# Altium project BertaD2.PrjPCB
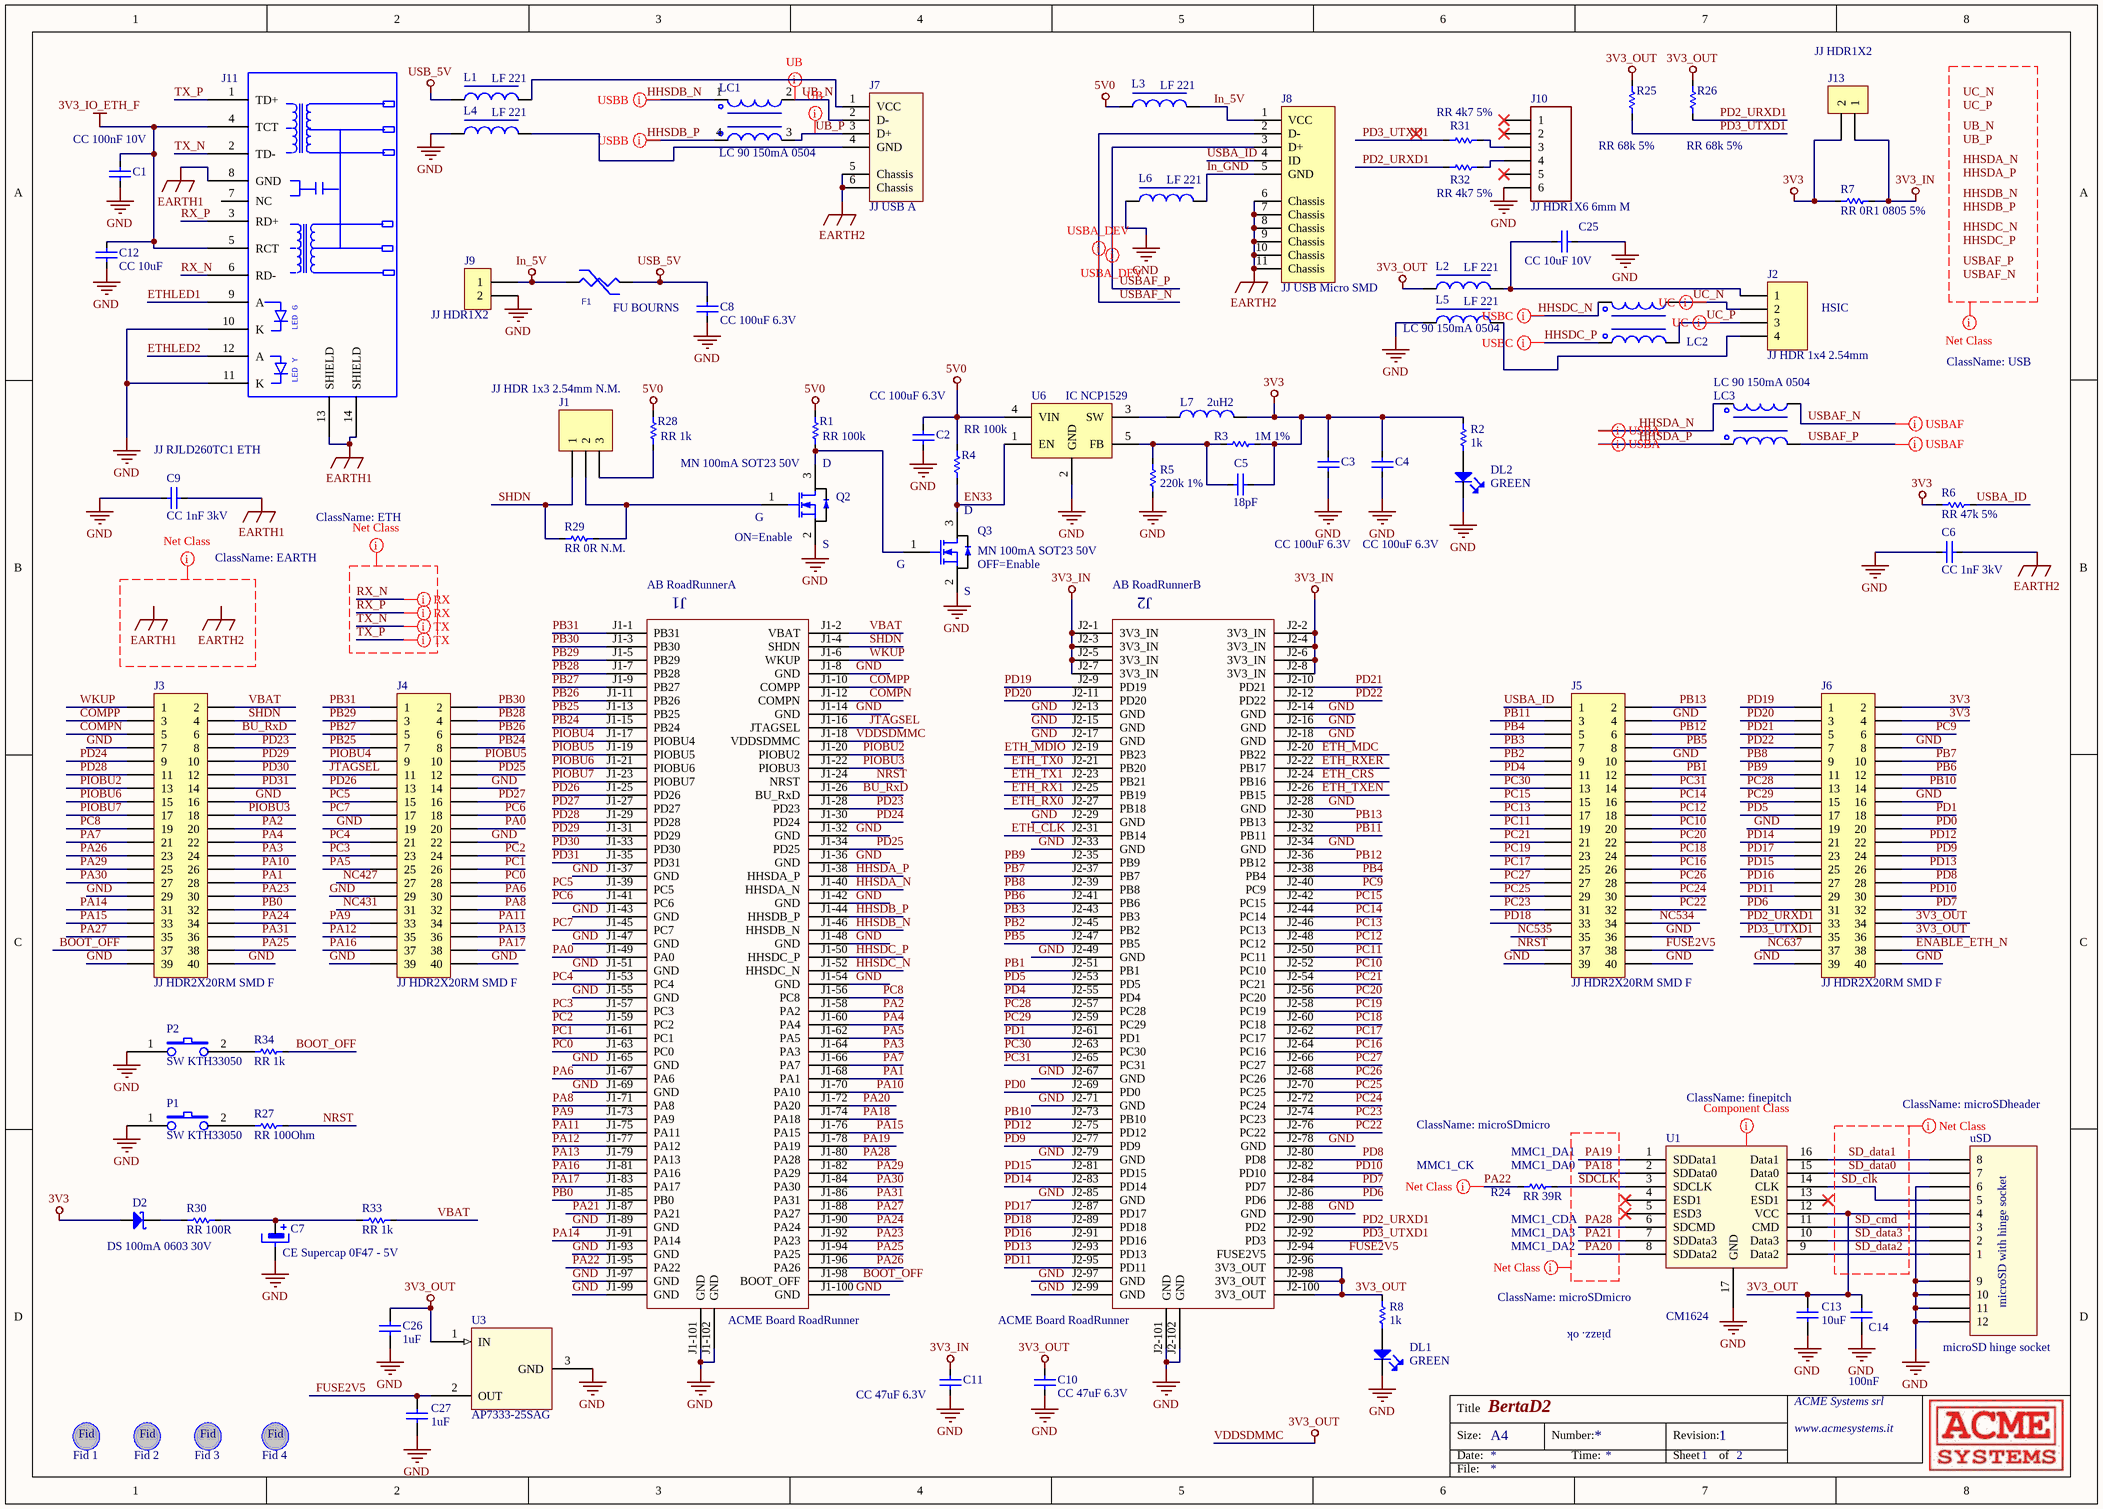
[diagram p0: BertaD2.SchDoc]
2 sheets, 108 parts. Net scope: global (net labels, ports and power ports of the same name join across sheets).
Board files: BertaD2_pan.PCBDOC, BertaD2.PcbDoc
Sheets:
  BertaD2.SchDoc
  BertaD2_ETH.SchDoc

## Sheet BertaD2.SchDoc: BertaD2
size A3; Organization: ACME Systems srl; Address2: www.acmesystems.it; Revision: 1; SheetNumber: 1; SheetTotal: 2

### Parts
AB_RoadRunner  ACME Board RoadRunner  [AB RoadRunner]  (parts A,B of 2)
C1  CC 100nF 10V  [CC 0402S 1005m SOLDER]
C2  CC 100uF 6.3V  [CC 1206 (3216 metric)]
C3  CC 100uF 6.3V  [CC 1206 (3216 metric)]
C4  CC 100uF 6.3V  [CC 1206 (3216 metric)]
C5  18pF  [CC 0402S 1005m SOLDER]
C6  CC 1nF 3kV  [CC 1808 (4520 metric)]
C7  CE Supercap 0F47 - 5V  [Supercap AVX 8x16x18]
C8  CC 100uF 6.3V  [CC 1206 (3216 metric)]
C9  CC 1nF 3kV  [CC 1808 (4520 metric)]
C10  CC 47uF 6.3V  [CC 1206 (3216 metric)]
C11  CC 47uF 6.3V  [CC 1206 (3216 metric)]
C12  CC 10uF  [CC 0805 (2012 metric)]
C13  10uF  [CC 0805 (2012 metric)]
C14  100nF  [CC 0402S 1005m SOLDER]
C25  CC 10uF 10V  [CC 0805 (2012 metric)]
C26  1uF  [CC 0603 (1608 metric)]
C27  1uF  [CC 0603 (1608 metric)]
D2  DS 100mA 0603 30V  [DD 0603]
DL1  GREEN  [DL 0603 (1608 metric) GREEN]
DL2  GREEN  [DL 0603 (1608 metric) GREEN]
F1  FU BOURNS  [FU 1812 (4532 metric)]
Fid_1  FF ACME  [Fiducial 1mm_small]  (value not drawn)
Fid_2  FF ACME  [Fiducial 1mm_small]  (value not drawn)
Fid_3  FF ACME  [Fiducial 1mm_small]  (value not drawn)
Fid_4  FF ACME  [Fiducial 1mm_small]  (value not drawn)
J1  JJ HDR 1x3 2.54mm N.M.  [HDR 1x3]
J2  JJ HDR 1x4 2.54mm  [HDR1X4 - Female DualMount]
J3  JJ HDR2X20RM SMD F  [HDR2X20 SMD Female]
J4  JJ HDR2X20RM SMD F  [HDR2X20 SMD Female]
J5  JJ HDR2X20RM SMD F  [HDR2X20 SMD Female]
J6  JJ HDR2X20RM SMD F  [HDR2X20 SMD Female]
J7  JJ USB A  [USB2.0-4H4 3D FOX]
J8  JJ USB Micro SMD  [USB Micro B - Extended]
J9  JJ HDR1X2  [HDR1X2 NAKED]
J10  JJ HDR1X6 6mm M  [HDR1X6 3D]
J11  JJ RJLD260TC1 ETH  [RJLD-260TC1]
J13  JJ HDR1X2  [HDR1X2 NAKED]
L1  LF 221  [LL 0603 (1608 metric)]
L2  LF 221  [LL 0603 (1608 metric)]
L3  LF 221  [LL 0603 (1608 metric)]
L4  LF 221  [LL 0603 (1608 metric)]
L5  LF 221  [LL 0603 (1608 metric)]
L6  LF 221  [LL 0603 (1608 metric)]
L7  2uH2  [LL 0805 (2012 metric)]
LC1  LC 90 150mA 0504  [LC 0504 (1210 metric)]
LC2  LC 90 150mA 0504  [LC 0504 (1210 metric)]
LC3  LC 90 150mA 0504  [LC 0504 (1210 metric)]
P1  SW KTH33050  [PULSANTE SMD S]
P2  SW KTH33050  [PULSANTE SMD S]
Q2  MN 100mA SOT23 50V  [SOT23 for IRLML6402]
Q3  MN 100mA SOT23 50V  [SOT23 for IRLML6402]
R1  RR 100k  [CC 0402S 1005m SOLDER]
R2  1k  [CC 0402S 1005m SOLDER]
R3  1M 1%  [CC 0402S 1005m SOLDER]
R4  RR 100k  [CC 0402S 1005m SOLDER]
R5  220k 1%  [CC 0402S 1005m SOLDER]
R6  RR 47k 5%  [RR 0402S 1005m SOLDER]
R7  RR 0R1 0805 5%  [RR 1206 (3216 metric)]
R8  1k  [CC 0402S 1005m SOLDER]
R24  RR 39R  [RR 0402S 1005m SOLDER]
R25  RR 68k 5%  [RR 0402S 1005m SOLDER]
R26  RR 68k 5%  [RR 0402S 1005m SOLDER]
R27  RR 100Ohm  [CC 0402S 1005m SOLDER]
R28  RR 1k  [CC 0402S 1005m SOLDER]
R29  RR 0R N.M.  [CC 0402S 1005m SOLDER]
R30  RR 100R  [RR 0603 (1608 metric)]
R31  RR 4k7 5%  [RR 0402S 1005m SOLDER]
R32  RR 4k7 5%  [RR 0402S 1005m SOLDER]
R33  RR 1k  [CC 0402S 1005m SOLDER]
R34  RR 1k  [CC 0402S 1005m SOLDER]
U1  CM1624  [CM1624]
U3  AP7333-25SAG  [SOT23 generic]
U6  IC NCP1529  [IC SOT23-5]
uSD  microSD hinge socket  [microSDHinge JAE E]

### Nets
3V3: C3.1 C4.1 C5.2 D2.A J6.2 J6.4 J13.2 L7.2 R2.1 R3.2 R6.1 R7.1
3V3_IN: AB_RoadRunner.J2-1(3V3_IN) AB_RoadRunner.J2-2(3V3_IN) AB_RoadRunner.J2-3(3V3_IN) AB_RoadRunner.J2-4(3V3_IN) AB_RoadRunner.J2-5(3V3_IN) AB_RoadRunner.J2-6(3V3_IN) AB_RoadRunner.J2-7(3V3_IN) AB_RoadRunner.J2-8(3V3_IN) C11.1 J13.1 R7.2
3V3_IO_ETH_F: C1.1 C12.1 J11.4(TCT) J11.5(RCT)
3V3_OUT: AB_RoadRunner.J1-18(VDDSDMMC) AB_RoadRunner.J2-96(3V3_OUT) AB_RoadRunner.J2-98(3V3_OUT) AB_RoadRunner.J2-100(3V3_OUT) C10.1 C13.1 C14.1 C26.2 J6.34 J6.36 L2.1 R8.1 R25.2 R26.2 U1.12(VCC) U3.1(IN) uSD.4  [also labelled VDDSDMMC]
5V0: C2.1 L3.1 R1.1 R4.1 R28.1 U6.4(VIN)
EARTH1: C9.2 J11.8(GND) J11.13(SHIELD) J11.14(SHIELD)
EARTH2: C6.2 J7.5(Chassis) J7.6(Chassis) J8.6(Chassis) J8.7(Chassis) J8.8(Chassis) J8.9(Chassis) J8.10(Chassis) J8.11(Chassis)
GND: AB_RoadRunner.J1-8(GND) AB_RoadRunner.J1-14(GND) AB_RoadRunner.J1-32(GND) AB_RoadRunner.J1-36(GND) AB_RoadRunner.J1-37(GND) AB_RoadRunner.J1-42(GND) AB_RoadRunner.J1-43(GND) AB_RoadRunner.J1-47(GND) AB_RoadRunner.J1-48(GND) AB_RoadRunner.J1-51(GND) AB_RoadRunner.J1-54(GND) AB_RoadRunner.J1-55(GND) AB_RoadRunner.J1-65(GND) AB_RoadRunner.J1-69(GND) AB_RoadRunner.J1-89(GND) AB_RoadRunner.J1-93(GND) AB_RoadRunner.J1-97(GND) AB_RoadRunner.J1-99(GND) AB_RoadRunner.J1-100(GND) AB_RoadRunner.J1-101(GND) AB_RoadRunner.J1-102(GND) AB_RoadRunner.J2-13(GND) AB_RoadRunner.J2-14(GND) AB_RoadRunner.J2-15(GND) AB_RoadRunner.J2-16(GND) AB_RoadRunner.J2-17(GND) AB_RoadRunner.J2-18(GND) AB_RoadRunner.J2-28(GND) AB_RoadRunner.J2-29(GND) AB_RoadRunner.J2-33(GND) AB_RoadRunner.J2-34(GND) AB_RoadRunner.J2-49(GND) AB_RoadRunner.J2-67(GND) AB_RoadRunner.J2-71(GND) AB_RoadRunner.J2-78(GND) AB_RoadRunner.J2-79(GND) AB_RoadRunner.J2-85(GND) AB_RoadRunner.J2-88(GND) AB_RoadRunner.J2-97(GND) AB_RoadRunner.J2-99(GND) AB_RoadRunner.J2-101(GND) AB_RoadRunner.J2-102(GND) C1.2 C2.2 C3.2 C4.2 C6.1 C7.2 C8.2 C9.1 C10.2 C11.2 C12.2 C13.2 C14.2 C25.2 C26.1 C27.2 DL1.K DL2.K J3.7 J3.16 J3.29 J3.39 J3.40 J4.14 J4.19 J4.22 J4.29 J4.39 J4.40 J5.4 J5.10 J5.36 J5.39 J5.40 J6.8 J6.16 J6.19 J6.39 J6.40 J9.2 J10.6 J11.10(K) J11.11(K) L4.1 L5.1 L6.1 P1.1 P2.1 Q2.2(S) Q3.2(S) R5.2 U1.17(GND) U3.3(GND) U6.2(GND) uSD.6 uSD.9 uSD.10 uSD.11 uSD.12
In_5V: F1.1 J8.1(VCC) J9.1 L3.2
USB_5V: C8.1 F1.2 L1.1
BOOT_OFF: AB_RoadRunner.J1-98(BOOT_OFF) J3.37 R34.2
BU_RxD: AB_RoadRunner.J1-26(BU_RxD) J3.6
COMPN: AB_RoadRunner.J1-12(COMPN) J3.5
COMPP: AB_RoadRunner.J1-10(COMPP) J3.3
EN33: Q3.3(D) R4.2 U6.1(EN)
ENABLE_ETH_N: J6.38
ETH_CLK: AB_RoadRunner.J2-31(PB14)
ETH_CRS: AB_RoadRunner.J2-24(PB16)
ETH_MDC: AB_RoadRunner.J2-20(PB22)
ETH_MDIO: AB_RoadRunner.J2-19(PB23)
ETH_RX0: AB_RoadRunner.J2-27(PB18)
ETH_RX1: AB_RoadRunner.J2-25(PB19)
ETH_RXER: AB_RoadRunner.J2-22(PB17)
ETH_TX0: AB_RoadRunner.J2-21(PB20)
ETH_TX1: AB_RoadRunner.J2-23(PB21)
ETH_TXEN: AB_RoadRunner.J2-26(PB15)
ETHLED1: J11.9(A)
ETHLED2: J11.12(A)
FUSE2V5: AB_RoadRunner.J2-94(FUSE2V5) C27.1 J5.38 U3.2(OUT)
HHSDA_N: AB_RoadRunner.J1-40(HHSDA_N) LC3.4
HHSDA_P: AB_RoadRunner.J1-38(HHSDA_P) LC3.1
HHSDB_N: AB_RoadRunner.J1-46(HHSDB_N) LC1.1
HHSDB_P: AB_RoadRunner.J1-44(HHSDB_P) LC1.4
HHSDC_N: AB_RoadRunner.J1-52(HHSDC_N) LC2.4
HHSDC_P: AB_RoadRunner.J1-50(HHSDC_P) LC2.1
In_GND: J8.5(GND) L6.2
JTAGSEL: AB_RoadRunner.J1-16(JTAGSEL) J4.11
NC427: J4.27
NC431: J4.31
NC534: J5.34
NC535: J5.35
NC637: J6.37
NRST: AB_RoadRunner.J1-24(NRST) J5.37 R27.2
PA0: AB_RoadRunner.J1-49(PA0) J4.20
PA1: AB_RoadRunner.J1-68(PA1) J3.28
PA2: AB_RoadRunner.J1-58(PA2) J3.20
PA3: AB_RoadRunner.J1-64(PA3) J3.24
PA4: AB_RoadRunner.J1-60(PA4) J3.22
PA5: AB_RoadRunner.J1-62(PA5) J4.25
PA6: AB_RoadRunner.J1-67(PA6) J4.30
PA7: AB_RoadRunner.J1-66(PA7) J3.21
PA8: AB_RoadRunner.J1-71(PA8) J4.32
PA9: AB_RoadRunner.J1-73(PA9) J4.33
PA10: AB_RoadRunner.J1-70(PA10) J3.26
PA11: AB_RoadRunner.J1-75(PA11) J4.34
PA12: AB_RoadRunner.J1-77(PA12) J4.35
PA13: AB_RoadRunner.J1-79(PA13) J4.36
PA14: AB_RoadRunner.J1-91(PA14) J3.31
PA15: AB_RoadRunner.J1-76(PA15) J3.33
PA16: AB_RoadRunner.J1-81(PA16) J4.37
PA17: AB_RoadRunner.J1-83(PA17) J4.38
PA18: AB_RoadRunner.J1-74(PA18) U1.2(SDData0)
PA19: AB_RoadRunner.J1-78(PA19) U1.1(SDData1)
PA20: AB_RoadRunner.J1-72(PA20) U1.8(SDData2)
PA21: AB_RoadRunner.J1-87(PA21) U1.7(SDData3)
PA22: AB_RoadRunner.J1-95(PA22) R24.1
PA23: AB_RoadRunner.J1-92(PA23) J3.30
PA24: AB_RoadRunner.J1-90(PA24) J3.34
PA25: AB_RoadRunner.J1-94(PA25) J3.38
PA26: AB_RoadRunner.J1-96(PA26) J3.23
PA27: AB_RoadRunner.J1-88(PA27) J3.35
PA28: AB_RoadRunner.J1-80(PA28) U1.6(SDCMD)
PA29: AB_RoadRunner.J1-82(PA29) J3.25
PA30: AB_RoadRunner.J1-84(PA30) J3.27
PA31: AB_RoadRunner.J1-86(PA31) J3.36
PB0: AB_RoadRunner.J1-85(PB0) J3.32
PB1: AB_RoadRunner.J2-51(PB1) J5.12
PB2: AB_RoadRunner.J2-45(PB2) J5.9
PB3: AB_RoadRunner.J2-43(PB3) J5.7
PB4: AB_RoadRunner.J2-38(PB4) J5.5
PB5: AB_RoadRunner.J2-47(PB5) J5.8
PB6: AB_RoadRunner.J2-41(PB6) J6.12
PB7: AB_RoadRunner.J2-37(PB7) J6.10
PB8: AB_RoadRunner.J2-39(PB8) J6.9
PB9: AB_RoadRunner.J2-35(PB9) J6.11
PB10: AB_RoadRunner.J2-73(PB10) J6.14
PB11: AB_RoadRunner.J2-32(PB11) J5.3
PB12: AB_RoadRunner.J2-36(PB12) J5.6
PB13: AB_RoadRunner.J2-30(PB13) J5.2
PB24: AB_RoadRunner.J1-15(PB24) J4.8
PB25: AB_RoadRunner.J1-13(PB25) J4.7
PB26: AB_RoadRunner.J1-11(PB26) J4.6
PB27: AB_RoadRunner.J1-9(PB27) J4.5
PB28: AB_RoadRunner.J1-7(PB28) J4.4
PB29: AB_RoadRunner.J1-5(PB29) J4.3
PB30: AB_RoadRunner.J1-3(PB30) J4.2
PB31: AB_RoadRunner.J1-1(PB31) J4.1
PC0: AB_RoadRunner.J1-63(PC0) J4.28
PC1: AB_RoadRunner.J1-61(PC1) J4.26
PC2: AB_RoadRunner.J1-59(PC2) J4.24
PC3: AB_RoadRunner.J1-57(PC3) J4.23
PC4: AB_RoadRunner.J1-53(PC4) J4.21
PC5: AB_RoadRunner.J1-39(PC5) J4.15
PC6: AB_RoadRunner.J1-41(PC6) J4.18
PC7: AB_RoadRunner.J1-45(PC7) J4.17
PC8: AB_RoadRunner.J1-56(PC8) J3.19
PC9: AB_RoadRunner.J2-40(PC9) J6.6
PC10: AB_RoadRunner.J2-52(PC10) J5.20
PC11: AB_RoadRunner.J2-50(PC11) J5.19
PC12: AB_RoadRunner.J2-48(PC12) J5.18
PC13: AB_RoadRunner.J2-46(PC13) J5.17
PC14: AB_RoadRunner.J2-44(PC14) J5.16
PC15: AB_RoadRunner.J2-42(PC15) J5.15
PC16: AB_RoadRunner.J2-64(PC16) J5.26
PC17: AB_RoadRunner.J2-62(PC17) J5.25
PC18: AB_RoadRunner.J2-60(PC18) J5.24
PC19: AB_RoadRunner.J2-58(PC19) J5.23
PC20: AB_RoadRunner.J2-56(PC20) J5.22
PC21: AB_RoadRunner.J2-54(PC21) J5.21
PC22: AB_RoadRunner.J2-76(PC22) J5.32
PC23: AB_RoadRunner.J2-74(PC23) J5.31
PC24: AB_RoadRunner.J2-72(PC24) J5.30
PC25: AB_RoadRunner.J2-70(PC25) J5.29
PC26: AB_RoadRunner.J2-68(PC26) J5.28
PC27: AB_RoadRunner.J2-66(PC27) J5.27
PC28: AB_RoadRunner.J2-57(PC28) J6.13
PC29: AB_RoadRunner.J2-59(PC29) J6.15
PC30: AB_RoadRunner.J2-63(PC30) J5.13
PC31: AB_RoadRunner.J2-65(PC31) J5.14
PD0: AB_RoadRunner.J2-69(PD0) J6.20
PD1: AB_RoadRunner.J2-61(PD1) J6.18
PD2_URXD1: AB_RoadRunner.J2-90(PD2) J6.33 R26.1 R32.2
PD3_UTXD1: AB_RoadRunner.J2-92(PD3) J6.35 R25.1 R31.2
PD4: AB_RoadRunner.J2-55(PD4) J5.11
PD5: AB_RoadRunner.J2-53(PD5) J6.17
PD6: AB_RoadRunner.J2-86(PD6) J6.31
PD7: AB_RoadRunner.J2-84(PD7) J6.32
PD8: AB_RoadRunner.J2-80(PD8) J6.28
PD9: AB_RoadRunner.J2-77(PD9) J6.24
PD10: AB_RoadRunner.J2-82(PD10) J6.30
PD11: AB_RoadRunner.J2-95(PD11) J6.29
PD12: AB_RoadRunner.J2-75(PD12) J6.22
PD13: AB_RoadRunner.J2-93(PD13) J6.26
PD14: AB_RoadRunner.J2-83(PD14) J6.21
PD15: AB_RoadRunner.J2-81(PD15) J6.25
PD16: AB_RoadRunner.J2-91(PD16) J6.27
PD17: AB_RoadRunner.J2-87(PD17) J6.23
PD18: AB_RoadRunner.J2-89(PD18) J5.33
PD19: AB_RoadRunner.J2-9(PD19) J6.1
PD20: AB_RoadRunner.J2-11(PD20) J6.3
PD21: AB_RoadRunner.J2-10(PD21) J6.5
PD22: AB_RoadRunner.J2-12(PD22) J6.7
PD23: AB_RoadRunner.J1-28(PD23) J3.8
PD24: AB_RoadRunner.J1-30(PD24) J3.9
PD25: AB_RoadRunner.J1-34(PD25) J4.12
PD26: AB_RoadRunner.J1-25(PD26) J4.13
PD27: AB_RoadRunner.J1-27(PD27) J4.16
PD28: AB_RoadRunner.J1-29(PD28) J3.11
PD29: AB_RoadRunner.J1-31(PD29) J3.10
PD30: AB_RoadRunner.J1-33(PD30) J3.12
PD31: AB_RoadRunner.J1-35(PD31) J3.14
PIOBU2: AB_RoadRunner.J1-20(PIOBU2) J3.13
PIOBU3: AB_RoadRunner.J1-22(PIOBU3) J3.18
PIOBU4: AB_RoadRunner.J1-17(PIOBU4) J4.9
PIOBU5: AB_RoadRunner.J1-19(PIOBU5) J4.10
PIOBU6: AB_RoadRunner.J1-21(PIOBU6) J3.15
PIOBU7: AB_RoadRunner.J1-23(PIOBU7) J3.17
RX_N: J11.6(RD-)
RX_P: J11.3(RD+)
SD_clk: U1.14(CLK) uSD.5
SD_cmd: U1.11(CMD) uSD.3
SD_data0: U1.15(Data0) uSD.7
SD_data1: U1.16(Data1) uSD.8
SD_data2: U1.9(Data2) uSD.1
SD_data3: U1.10(Data3) uSD.2
SDCLK: R24.2 U1.3(SDCLK)
SHDN: AB_RoadRunner.J1-4(SHDN) J1.1 J3.4 R29.1
TX_N: J11.2(TD-)
TX_P: J11.1(TD+)
UB_N: J7.2(D-) LC1.2
UB_P: J7.3(D+) LC1.3
UC_N: J2.2 LC2.3
UC_P: J2.3 LC2.2
USBA_ID: J5.1 J8.4(ID) R6.2
USBAF_N: J8.2(D-) LC3.3
USBAF_P: J8.3(D+) LC3.2
VBAT: AB_RoadRunner.J1-2(VBAT) J3.2 R33.2
WKUP: AB_RoadRunner.J1-6(WKUP) J3.1
NetC5_1: C5.1 R3.1 R5.1 U6.5(FB)
NetC7_1: C7.1 R30.2 R33.1
NetC25_1: C25.1 J2.1 L2.2
NetD2_K: D2.K R30.1
NetDL1_A: DL1.A R8.2
NetDL2_A: DL2.A R2.2
NetJ1_2: J1.2 Q2.1(G) R29.2
NetJ1_3: J1.3 R28.2
NetJ2_4: J2.4 L5.2
NetJ7_1: J7.1(VCC) L1.2
NetJ7_4: J7.4(GND) L4.2
NetJ10_3: J10.3 R31.1
NetJ10_4: J10.4 R32.1
NetL7_1: L7.1 U6.3(SW)
NetP1_2: P1.2 R27.1
NetP2_2: P2.2 R34.1
NetQ2_3: Q2.3(D) Q3.1(G) R1.2

Not connected (* = marked no-connect by the designer): J10 1* 2* 5*; J11 7(NC); U1 4(ESD1)* 5(ESD3)* 13(ESD1)*

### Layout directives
differential pair: HHSDA_N, HHSDA_P, HHSDB_N, HHSDB_P, HHSDC_N, HHSDC_P, RX_N, RX_P, TX_N, TX_P, UB_N, UB_P, UC_N, UC_P, USBAF_N, USBAF_P
net class microSDmicro: PA18, PA19, PA20, PA21, PA22, PA28, SDCLK
net class microSDheader: SD_clk, SD_cmd, SD_data0, SD_data1, SD_data2, SD_data3
net class USB: HHSDA_N, HHSDA_P, HHSDB_N, HHSDB_P, HHSDC_N, HHSDC_P, UB_N, UB_P, UC_N, UC_P, USBAF_N, USBAF_P
net class ETH: RX_N, RX_P, TX_N, TX_P
net class EARTH: EARTH1, EARTH2
net class finepitch: (no net found under the mark)

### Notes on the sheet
- HSIC
- (near Q2) ON=Enable
- (near Q3) OFF=Enable
- MMC1_CK
- (near R24) MMC1_DA1
- (near R24) MMC1_DA0
- (near R24) MMC1_CDA
- (near R24) MMC1_DA3
- MMC1_DA2
- piazz. ok
- Labels drawn without touching a wire or pin: EARTH1, EARTH2, HHSDA_N, HHSDA_P, HHSDB_N, HHSDB_P, HHSDC_N, HHSDC_P, UB_N, UB_P, UC_N, UC_P, USBAF_N, USBAF_P

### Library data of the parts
AB_RoadRunner = AB RoadRunner
C1-C4 C6 C8-C12 C25 = CC Ceramic Capacitor: Capacitor, Multi Layer Ceramic
C5 C13 C14 C26 C27 = CC Ceramic: Capacitor, Multi Layer Ceramic
C7 = CE Supercap: Electrolytic Capacittor; Right: 20; Bottom: 10
D2 = DS Schottky Diode: Schottky Diode
DL1 DL2 = DL LED: LED Light-emitting diode; Right: 40; Bottom: 20
F1 = FUSE SMD: Bourns Fuse
J1 = JJ HDR 1x3 2.54mm
J3-J6 = JJ HDR2X20RM SMD F: Header 20X2 SMD Female reverse mount
J7 = JJ USB A: USB 2.0 type A; Right: 30; Bottom: 70
J8 = JJ USB Micro SMD: USB Micro B Digikey: 609-4050-2-ND
J9 J13 = JJ HDR1X2: Header, 2-Pin Dual Mount Female 2mm
J10 = JJ HDR1X6 6mm M: Header, 6-Pin Male 6mm
J11 = JJ RJLD260TC1 ETH: ETH connector RJLD-260TC1 TAIMAG; Right: 100; Bottom: 240
L1-L6 = LF Ferrite: Ferrite
L7 = LL Inductor: Power inductor 2uH2 0805; Right: 10; Bottom: 40
LC1-LC3 = LC Choke: Common Mode Choke Coil Film Type; Right: 10; Bottom: 40
P1 P2 = SW KTH33050: SWITCH TACT 6MM 160GF H=4.3MM; Right: 30; Bottom: 20
Q2 Q3 = MN 100mA SOT23 50V: 100mA N-Channel Logic MOSFET SOT23
R1-R8 R24-R34 = RR Resistor: Resistor
U1 = IC CM1624
U3 = AP7333: LDO Regulator SOT-23
U6 = IC NCP1529: 1.7MHz, 1A, High Efficiency, Low Ripple, Adjustable Output Voltage Step-down Converter
uSD = microSDHinge

## Sheet BertaD2_ETH.SchDoc: BertaD2_ETH
size A3; Organization: ACME Systems srl; Address2: www.acmesystems.it; Revision: 1; SheetNumber: 2; SheetTotal: 2
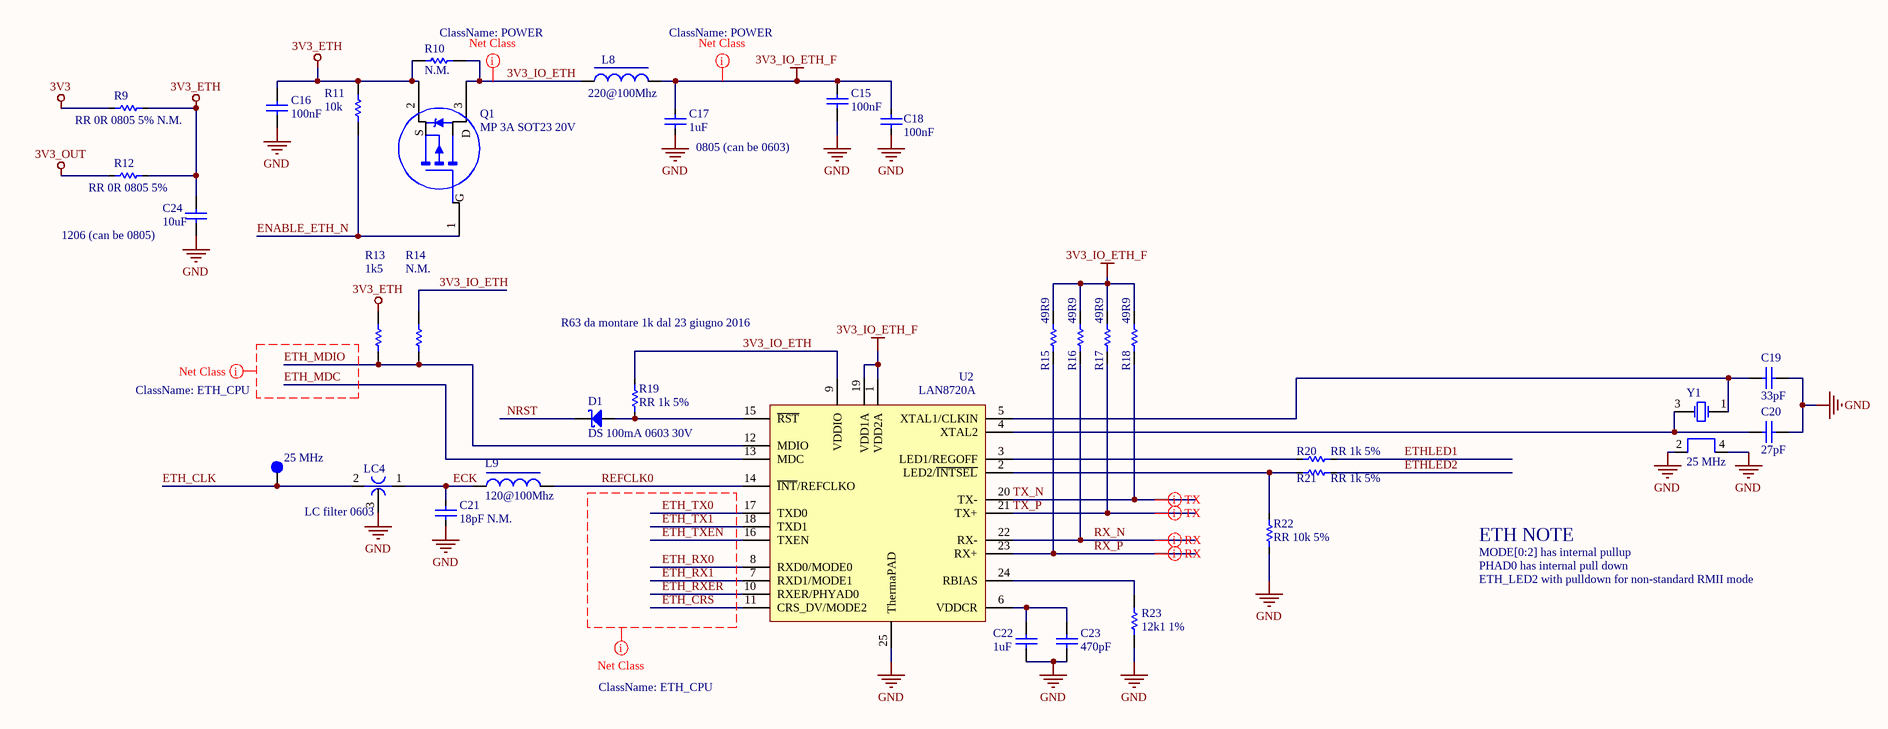
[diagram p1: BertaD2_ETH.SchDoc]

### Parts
25_MHz  GN TEST POINT  [TP 1.3mm]  (value not drawn)
C15  100nF  [CC 0402S 1005m SOLDER]
C16  100nF  [CC 0402S 1005m SOLDER]
C17  1uF  [CC 0805 (2012 metric)]
C18  100nF  [CC 0402S 1005m SOLDER]
C19  33pF  [CC 0402S 1005m SOLDER]
C20  27pF  [CC 0402S 1005m SOLDER]
C21  18pF N.M.  [CC 0402S 1005m SOLDER]
C22  1uF  [CC 0603 (1608 metric)]
C23  470pF  [CC 0402S 1005m SOLDER]
C24  10uF  [CC 1206 (3216 metric)]
D1  DS 100mA 0603 30V  [DD 0603]
L8  220@100Mhz  [LL 0603 (1608 metric)]
L9  120@100Mhz  [LL 0603 (1608 metric)]
LC4  LC filter 0603  [LC 0603 (1608 metric)]
Q1  MP 3A SOT23 20V  [SOT23 for IRLML6402]
R9  RR 0R 0805 5% N.M.  [RR 0805 (2012 metric)]
R10  N.M.  [RR 0603 (1608 metric)]
R11  10k  [RR 0402S 1005m SOLDER]
R12  RR 0R 0805 5%  [RR 0805 (2012 metric)]
R13  1k5  [RR 0402S 1005m SOLDER]
R14  N.M.  [RR 0402S 1005m SOLDER]
R15  49R9  [RR 0402S 1005m SOLDER]
R16  49R9  [RR 0402S 1005m SOLDER]
R17  49R9  [RR 0402S 1005m SOLDER]
R18  49R9  [RR 0402S 1005m SOLDER]
R19  RR 1k 5%  [RR 0402S 1005m SOLDER]
R20  RR 1k 5%  [RR 0402S 1005m SOLDER]
R21  RR 1k 5%  [RR 0402S 1005m SOLDER]
R22  RR 10k 5%  [RR 0402S 1005m SOLDER]
R23  12k1 1%  [RR 0402S 1005m SOLDER]
U2  LAN8720A  [QFN24 - 4x4mm]
Y1  25 MHz  [XT DFN-LCC 3.2x2.5]

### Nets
3V3: R9.1
3V3_ETH: C16.2 C24.1 Q1.2(S) R9.2 R10.1 R11.1 R12.2 R13.1
3V3_IO_ETH_F: C15.2 C17.1 C18.1 L8.2 R15.2 R16.2 R17.2 R18.2 U2.1(VDD2A) U2.19(VDD1A)
3V3_OUT: R12.1
GND: C15.1 C16.1 C17.2 C18.2 C19.2 C20.2 C21.2 C22.2 C23.2 C24.2 LC4.3 R22.1 R23.2 U2.25(ThermaPAD) Y1.2 Y1.4
3V3_IO_ETH: L8.1 Q1.3(D) R10.2 R14.1 R19.1 U2.9(VDDIO)
ECK: C21.1 L9.1 LC4.1
ENABLE_ETH_N: Q1.1(G) R11.2
ETH_CLK: 25_MHz.1 LC4.2
ETH_CRS: U2.11(CRS_DV/MODE2)
ETH_MDC: U2.13(MDC)
ETH_MDIO: R13.2 R14.2 U2.12(MDIO)
ETH_RX0: U2.8(RXD0/MODE0)
ETH_RX1: U2.7(RXD1/MODE1)
ETH_RXER: U2.10(RXER/PHYAD0)
ETH_TX0: U2.17(TXD0)
ETH_TX1: U2.18(TXD1)
ETH_TXEN: U2.16(TXEN)
ETHLED1: R20.2
ETHLED2: R21.2
NRST: D1.K
REFCLK0: L9.2 U2.14(~{INT}/REFCLKO)
RX_N: R16.1 U2.22(RX-)
RX_P: R15.1 U2.23(RX+)
TX_N: R18.1 U2.20(TX-)
TX_P: R17.1 U2.21(TX+)
NetC19_1: C19.1 U2.5(XTAL1/CLKIN) Y1.1(OSC1)
NetC20_1: C20.1 U2.4(XTAL2) Y1.3(OSC2)
NetC22_1: C22.1 C23.1 U2.6(VDDCR)
NetD1_A: D1.A R19.2 U2.15(~{RST})
NetR20_1: R20.1 U2.3(LED1/REGOFF)
NetR21_1: R21.1 R22.2 U2.2(LED2/~{INTSEL})
NetR23_1: R23.1 U2.24(RBIAS)

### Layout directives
differential pair: RX_N, RX_P, TX_N, TX_P
net class POWER: 3V3_IO_ETH, 3V3_IO_ETH_F
net class ETH_CPU: ETH_CRS, ETH_MDC, ETH_MDIO, ETH_RX0, ETH_RX1, ETH_RXER, ETH_TX0, ETH_TX1, ETH_TXEN

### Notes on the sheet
- (near C17) 0805 (can be 0603)
- (near C24) 1206 (can be 0805)
- R63 da montare 1k dal 23 giugno 2016
- ETH NOTE
- MODE[0:2] has internal pullup
- PHAD0 has internal pull down
- ETH_LED2 with pulldown for non-standard RMII mode

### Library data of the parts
25_MHz = GN TEST POINT: Test Point 1.3 mm; Right: 10; Bottom: 20
C15-C24 = CC Ceramic: Capacitor, Multi Layer Ceramic
D1 = DS Schottky Diode: Schottky Diode
L8 = LF Ferrite: Ferrite 220 Ohm 2A 0805; Right: 10; Bottom: 40
L9 = LF Ferrite: Ferrite 120 Ohm 0603; Right: 10; Bottom: 40
LC4 = LC EMI Filter: Ferrite 220 Ohm 2A 0805; Right: 10; Bottom: 40
Q1 = MP 3A SOT23 20V: 3A P-Channel Logic MOSFET SOT23
R9-R23 = RR Resistor: Resistor
U2 = IC LAN8720
Y1 = XT QUAD

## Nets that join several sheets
3V3: BertaD2 (12 pins), BertaD2_ETH (R9.1)
3V3_IO_ETH_F: BertaD2 (C1.1 C12.1 J11.4 J11.5), BertaD2_ETH (10 pins)
3V3_OUT: BertaD2 (17 pins), BertaD2_ETH (R12.1)
GND: BertaD2 (101 pins), BertaD2_ETH (16 pins)
ENABLE_ETH_N: BertaD2 (J6.38), BertaD2_ETH (Q1.1 R11.2)
ETH_CLK: BertaD2 (AB_RoadRunner.J2-31), BertaD2_ETH (25_MHz.1 LC4.2)
ETH_CRS: BertaD2 (AB_RoadRunner.J2-24), BertaD2_ETH (U2.11)
ETH_MDC: BertaD2 (AB_RoadRunner.J2-20), BertaD2_ETH (U2.13)
ETH_MDIO: BertaD2 (AB_RoadRunner.J2-19), BertaD2_ETH (R13.2 R14.2 U2.12)
ETH_RX0: BertaD2 (AB_RoadRunner.J2-27), BertaD2_ETH (U2.8)
ETH_RX1: BertaD2 (AB_RoadRunner.J2-25), BertaD2_ETH (U2.7)
ETH_RXER: BertaD2 (AB_RoadRunner.J2-22), BertaD2_ETH (U2.10)
ETH_TX0: BertaD2 (AB_RoadRunner.J2-21), BertaD2_ETH (U2.17)
ETH_TX1: BertaD2 (AB_RoadRunner.J2-23), BertaD2_ETH (U2.18)
ETH_TXEN: BertaD2 (AB_RoadRunner.J2-26), BertaD2_ETH (U2.16)
ETHLED1: BertaD2 (J11.9), BertaD2_ETH (R20.2)
ETHLED2: BertaD2 (J11.12), BertaD2_ETH (R21.2)
NRST: BertaD2 (AB_RoadRunner.J1-24 J5.37 R27.2), BertaD2_ETH (D1.K)
RX_N: BertaD2 (J11.6), BertaD2_ETH (R16.1 U2.22)
RX_P: BertaD2 (J11.3), BertaD2_ETH (R15.1 U2.23)
TX_N: BertaD2 (J11.2), BertaD2_ETH (R18.1 U2.20)
TX_P: BertaD2 (J11.1), BertaD2_ETH (R17.1 U2.21)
